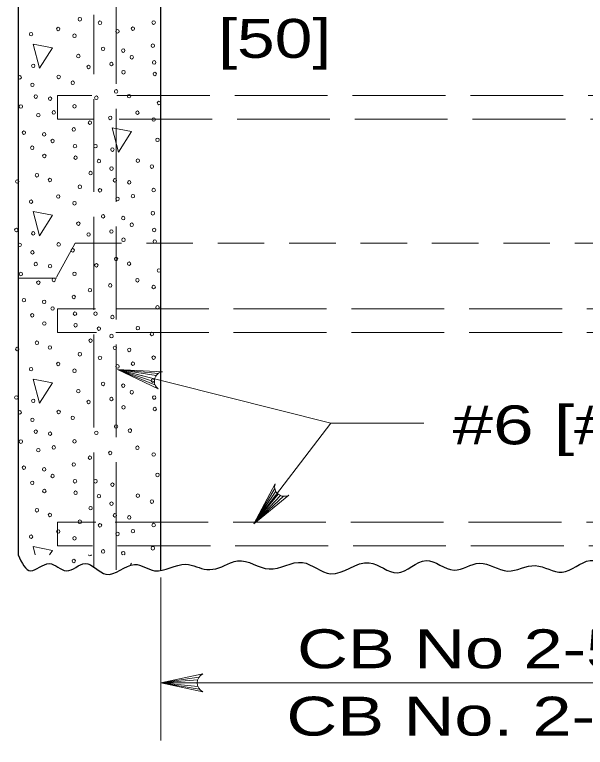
# Model space of a CAD drawing. Extents: x 1329.9 to 1363.9, y 715.5 to 737.5.
# Drawn here: x 1332.853 to 1335.139, y 728.698 to 731.635 of the extents above; entities that cross this region are included whole.
import ezdxf
from ezdxf.enums import TextEntityAlignment as Align

# ---------------------------------------------------------------- set-up
doc = ezdxf.new("R2010")
doc.units = 0
doc.header["$LTSCALE"] = 0.062
doc.linetypes.add('LONG_DASHED', pattern=[7.5, 6, -1.5])
doc.linetypes.add('MEDIUM_DASHED', pattern=[4.5, 3, -1.5])
doc.layers.add('1', color=7, linetype='Continuous', lineweight=13)

msp = doc.modelspace()

# ---------------------------------------------------------------- linework, layer by layer
at = {"layer": '1', "lineweight": 25}
for p, q in [((1333.43842, 729.84383), (1333.43842, 733.47708)), ((1332.86692, 732.80092), (1332.86692, 729.46942))]:
    msp.add_line(p, q, dxfattribs=at)
at = {"layer": '1', "linetype": 'LONG_DASHED'}
for p, q in [((1333.16925, 729.50833), (1333.16925, 731.63508)), ((1333.02425, 731.31067), (1333.02425, 731.21567)), ((1333.02425, 731.31067), (1333.16242, 731.31067)), ((1333.26267, 731.31067), (1338.07467, 731.31067)), ((1333.02425, 731.21567), (1333.167, 731.21567)), ((1333.27175, 731.21567), (1338.07467, 731.21567)), ((1333.02425, 730.45583), (1333.02425, 730.36083)), ((1333.02425, 730.45583), (1333.17608, 730.45583)), ((1333.25808, 730.45583), (1338.07925, 730.45583)), ((1333.02425, 730.36083), (1333.18067, 730.36083)), ((1333.25808, 730.36083), (1338.09292, 730.36083)), ((1333.02425, 729.60092), (1333.02425, 729.50592)), ((1333.02425, 729.60092), (1333.17833, 729.60092)), ((1333.25575, 729.60092), (1338.07692, 729.60092)), ((1333.02425, 729.50592), (1333.16467, 729.50592)), ((1333.26492, 729.50592), (1338.07692, 729.50592))]:
    msp.add_line(p, q, dxfattribs=at)
at = {"layer": '1', "linetype": 'MEDIUM_DASHED'}
for p, q in [((1333.095, 730.71958), (1333.02067, 730.58333)), ((1332.86708, 730.57925), (1333.02067, 730.57925))]:
    msp.add_line(p, q, dxfattribs=at)
at = {"layer": '1'}
for p, q in [((1333.265, 730.21225), (1334.11917, 729.997)), ((1333.41358, 730.175), (1333.265, 730.21225)), ((1333.41983, 730.18825), (1333.265, 730.21225)), ((1333.42833, 730.19683), (1333.265, 730.21225)), ((1333.41242, 730.16358), (1333.265, 730.21225)), ((1333.415, 730.1515), (1333.265, 730.21225)), ((1333.81167, 729.59417), (1334.11917, 729.997)), ((1334.49225, 729.997), (1334.11917, 729.997)), ((1333.89508, 729.7355), (1333.81167, 729.59417)), ((1333.89925, 729.72417), (1333.81167, 729.59417)), ((1333.90858, 729.71283), (1333.81167, 729.59417)), ((1333.91842, 729.707), (1333.81167, 729.59417)), ((1333.93042, 729.70417), (1333.81167, 729.59417)), ((1333.00408, 729.48742), (1332.92617, 729.50258)), ((1332.92617, 729.50258), (1332.93483, 729.46942)), ((1332.99258, 729.46942), (1333.00408, 729.48742)), ((1333.3165, 729.429), (1333.32117, 729.4365)), ((1333.43842, 729.37808), (1333.43842, 728.82842)), ((1333.43842, 729.37542), (1333.43842, 728.72567)), ((1333.59075, 728.97883), (1333.43842, 728.95625)), ((1333.58558, 728.96767), (1333.43842, 728.95625)), ((1333.584, 728.95625), (1333.43842, 728.95625)), ((1333.58667, 728.94183), (1333.43842, 728.95625)), ((1333.5925, 728.93133), (1333.43842, 728.95625)), ((1337.23308, 728.95625), (1333.43842, 728.95625))]:
    msp.add_line(p, q, dxfattribs=at)
at = {"layer": '1', "linetype": 'LONG_DASHED'}
for points in [[(1333.259, 729.40917), (1333.259, 729.46942), (1333.259, 733.37567)], [(1333.16925, 729.41842), (1333.16925, 729.46942), (1333.16925, 729.50833)]]:
    msp.add_lwpolyline(points, dxfattribs=at)
at = {"layer": '1'}
for points in [[(1332.92617, 731.5175), (1332.95175, 731.42017), (1333.00408, 731.50233)], [(1333.24333, 731.18167), (1333.269, 731.08433), (1333.32117, 731.1665)], [(1332.92617, 730.84592), (1332.95175, 730.7485), (1333.00408, 730.83067)], [(1332.92617, 730.17425), (1332.95175, 730.07692), (1333.00408, 730.15908)]]:
    msp.add_lwpolyline(points, close=True, dxfattribs=at)
at = {"layer": '1', "linetype": 'MEDIUM_DASHED'}
msp.add_lwpolyline([(1333.095, 730.71958), (1338.24792, 730.71958), (1338.32433, 730.57925)], dxfattribs=at)
at = {"layer": '1'}
for points in [[(1333.44533, 730.20358), (1333.265, 730.21225), (1333.42808, 730.13483)], [(1333.89625, 729.75375), (1333.81167, 729.59417), (1333.95108, 729.70892)], [(1333.60667, 728.92067), (1333.43842, 728.95625), (1333.60667, 728.99192)]]:
    msp.add_lwpolyline(points, dxfattribs=at)
at = {"layer": '1', "lineweight": 25}
msp.add_lwpolyline([(1333.43842, 729.40858), (1333.43842, 729.46942), (1333.43842, 729.84383)], dxfattribs=at)
at = {"layer": '1'}
for centre, start, end in [((1333.45059, 730.16568), 98.01033, 233.83646), ((1333.93272, 729.74239), 162.86757, 298.6937)]:
    msp.add_arc(centre, 0.03822, start, end, dxfattribs=at)
for centre, major_axis in [((1333.11378, 731.61691), (0, 0.00718)), ((1333.19456, 731.6027), (0, 0.00718)), ((1333.40957, 731.60354), (0, 0.00718)), ((1332.91849, 731.55703), (0, 0.00718)), ((1333.02724, 731.5779), (0, 0.00718)), ((1333.26477, 731.56822), (0, 0.00718)), ((1333.32647, 731.57913), (0, 0.00718)), ((1333.09237, 731.5507), (0, 0.00718)), ((1333.20715, 731.49814), (0, 0.00718)), ((1333.40645, 731.51079), (0, 0.00718)), ((1333.10781, 731.4691), (0, 0.00718)), ((1333.28798, 731.49115), (0, 0.00718)), ((1333.32165, 731.46456), (0, 0.00718)), ((1333.24056, 731.43736), (0, 0.00718)), ((1333.41158, 731.44368), (0, 0.00718)), ((1332.92706, 731.43008), (0, 0.00718)), ((1333.14894, 731.42555), (0, 0.00718)), ((1332.87314, 731.38385), (0, 0.00718)), ((1333.02899, 731.38564), (0, 0.00718)), ((1333.28882, 731.40439), (0, 0.00718)), ((1333.41412, 731.39745), (0, 0.00718)), ((1332.92362, 731.35391), (0, 0.00718)), ((1333.0855, 731.36208), (0, 0.00718)), ((1333.25885, 731.32732), (0, 0.00718)), ((1332.93737, 731.30678), (0, 0.00718)), ((1332.99473, 731.29855), (0, 0.00718)), ((1333.18003, 731.30197), (0, 0.00718)), ((1333.31108, 731.30829), (0, 0.00718)), ((1332.87736, 731.26687), (0, 0.00718)), ((1333.09237, 731.26771), (0, 0.00718)), ((1333.43098, 731.28109), (0, 0.00718)), ((1332.94757, 731.2324), (0, 0.00718)), ((1333.00927, 731.24331), (0, 0.00718)), ((1333.34444, 731.24208), (0, 0.00718)), ((1333.15428, 731.20217), (0, 0.00718)), ((1333.23569, 731.2212), (0, 0.00718)), ((1333.40957, 731.21488), (0, 0.00718)), ((1333.08925, 731.17497), (0, 0.00718)), ((1332.88995, 731.16232), (0, 0.00718)), ((1332.97078, 731.15533), (0, 0.00718)), ((1333.00446, 731.12874), (0, 0.00718)), ((1333.42501, 731.13327), (0, 0.00718)), ((1332.92336, 731.10154), (0, 0.00718)), ((1333.09438, 731.10786), (0, 0.00718)), ((1333.17664, 731.10786), (0, 0.00718)), ((1333.24426, 731.09426), (0, 0.00718)), ((1332.97163, 731.06857), (0, 0.00718)), ((1333.09692, 731.06163), (0, 0.00718)), ((1333.19033, 731.04803), (0, 0.00718)), ((1333.34619, 731.04982), (0, 0.00718)), ((1333.4027, 731.02626), (0, 0.00718)), ((1333.15687, 730.99995), (0, 0.00718)), ((1333.24082, 731.01809), (0, 0.00718)), ((1332.86283, 730.96614), (0, 0.00718)), ((1332.94165, 730.9915), (0, 0.00718)), ((1332.99388, 730.97247), (0, 0.00718)), ((1333.25457, 730.97096), (0, 0.00718)), ((1333.11378, 730.94527), (0, 0.00718)), ((1333.31193, 730.96273), (0, 0.00718)), ((1333.02724, 730.90626), (0, 0.00718)), ((1333.19456, 730.93105), (0, 0.00718)), ((1333.32647, 730.90749), (0, 0.00718)), ((1333.40957, 730.93189), (0, 0.00718)), ((1332.91849, 730.88538), (0, 0.00718)), ((1333.09237, 730.87905), (0, 0.00718)), ((1333.26477, 730.89657), (0, 0.00718)), ((1333.20715, 730.8265), (0, 0.00718)), ((1333.28798, 730.8195), (0, 0.00718)), ((1333.40645, 730.83915), (0, 0.00718)), ((1333.10781, 730.79745), (0, 0.00718)), ((1333.32165, 730.79292), (0, 0.00718)), ((1332.85944, 730.77204), (0, 0.00718)), ((1333.24056, 730.76571), (0, 0.00718)), ((1333.41158, 730.77204), (0, 0.00718)), ((1332.92706, 730.75844), (0, 0.00718)), ((1333.14894, 730.7539), (0, 0.00718)), ((1333.28882, 730.73275), (0, 0.00718)), ((1332.87314, 730.71221), (0, 0.00718)), ((1333.02899, 730.714), (0, 0.00718)), ((1333.41412, 730.72581), (0, 0.00718)), ((1332.92362, 730.68226), (0, 0.00718)), ((1333.0855, 730.69043), (0, 0.00718)), ((1333.25885, 730.65568), (0, 0.00718)), ((1332.93737, 730.63514), (0, 0.00718)), ((1332.99473, 730.62691), (0, 0.00718)), ((1333.18003, 730.63032), (0, 0.00718)), ((1333.31108, 730.63665), (0, 0.00718)), ((1332.87736, 730.59523), (0, 0.00718)), ((1333.09237, 730.59607), (0, 0.00718)), ((1333.43098, 730.60945), (0, 0.00718)), ((1332.94757, 730.56075), (0, 0.00718)), ((1333.00927, 730.57167), (0, 0.00718)), ((1333.34444, 730.57043), (0, 0.00718)), ((1333.15428, 730.53053), (0, 0.00718)), ((1333.23569, 730.54956), (0, 0.00718)), ((1333.40957, 730.54323), (0, 0.00718)), ((1333.08925, 730.50333), (0, 0.00718)), ((1332.88995, 730.49068), (0, 0.00718)), ((1332.97078, 730.48368), (0, 0.00718)), ((1333.00446, 730.45709), (0, 0.00718)), ((1333.09438, 730.43622), (0, 0.00718)), ((1333.17664, 730.43622), (0, 0.00718)), ((1333.42501, 730.46163), (0, 0.00718)), ((1332.92336, 730.42989), (0, 0.00718)), ((1333.24426, 730.42262), (0, 0.00718)), ((1332.97163, 730.39693), (0, 0.00718)), ((1333.09692, 730.38998), (0, 0.00718)), ((1333.34619, 730.37818), (0, 0.00718)), ((1333.19033, 730.37638), (0, 0.00718)), ((1333.4027, 730.35461), (0, 0.00718)), ((1332.94165, 730.31985), (0, 0.00718)), ((1333.15687, 730.32831), (0, 0.00718)), ((1333.24082, 730.34644), (0, 0.00718)), ((1332.86283, 730.2945), (0, 0.00718)), ((1332.99388, 730.30082), (0, 0.00718)), ((1333.25457, 730.29931), (0, 0.00718)), ((1333.31193, 730.29109), (0, 0.00718)), ((1333.11378, 730.27362), (0, 0.00718)), ((1333.19456, 730.25941), (0, 0.00718)), ((1333.40957, 730.26025), (0, 0.00718)), ((1333.02724, 730.23461), (0, 0.00718)), ((1333.32647, 730.23584), (0, 0.00718)), ((1332.91849, 730.21373), (0, 0.00718)), ((1333.09237, 730.20741), (0, 0.00718)), ((1333.26477, 730.22493), (0, 0.00718)), ((1333.20715, 730.15485), (0, 0.00718)), ((1333.28798, 730.14786), (0, 0.00718)), ((1333.40645, 730.1675), (0, 0.00718)), ((1333.10781, 730.1258), (0, 0.00718)), ((1333.32165, 730.12127), (0, 0.00718)), ((1332.85944, 730.10039), (0, 0.00718)), ((1332.92706, 730.08679), (0, 0.00718)), ((1333.24056, 730.09407), (0, 0.00718)), ((1333.14894, 730.08226), (0, 0.00718)), ((1333.28882, 730.0611), (0, 0.00718)), ((1333.41412, 730.05416), (0, 0.00718)), ((1332.87314, 730.04056), (0, 0.00718)), ((1333.02899, 730.04235), (0, 0.00718)), ((1332.92362, 730.01062), (0, 0.00718)), ((1333.0855, 730.01879), (0, 0.00718)), ((1333.25885, 729.98403), (0, 0.00718)), ((1333.31448, 729.96761), (-0.00095, 0.00712)), ((1332.93737, 729.96349), (0, 0.00718)), ((1332.99473, 729.95526), (0, 0.00718)), ((1333.18003, 729.95868), (0, 0.00718)), ((1332.87736, 729.92358), (0, 0.00718)), ((1333.09237, 729.92442), (0, 0.00718)), ((1332.94757, 729.88911), (0, 0.00718)), ((1333.00927, 729.90002), (0, 0.00718)), ((1333.23569, 729.87791), (0, 0.00718)), ((1333.34444, 729.89879), (0, 0.00718)), ((1333.15428, 729.85888), (0, 0.00718)), ((1333.40957, 729.87159), (0, 0.00718)), ((1332.88995, 729.81903), (0, 0.00718)), ((1333.08925, 729.83168), (0, 0.00718)), ((1332.97078, 729.81203), (0, 0.00718)), ((1333.42501, 729.78998), (0, 0.00718)), ((1333.00446, 729.78545), (0, 0.00718)), ((1333.09438, 729.76457), (0, 0.00718)), ((1333.17664, 729.76457), (0, 0.00718)), ((1332.92336, 729.75825), (0, 0.00718)), ((1333.24426, 729.75097), (0, 0.00718)), ((1332.97163, 729.72528), (0, 0.00718)), ((1333.09692, 729.71834), (0, 0.00718)), ((1333.19033, 729.70474), (0, 0.00718)), ((1333.34619, 729.70653), (0, 0.00718)), ((1333.24082, 729.67479), (0, 0.00718)), ((1333.4027, 729.68297), (0, 0.00718)), ((1332.94165, 729.64821), (0, 0.00718)), ((1333.15687, 729.65666), (0, 0.00718)), ((1332.99388, 729.62918), (0, 0.00718)), ((1333.25457, 729.62767), (0, 0.00718)), ((1333.31193, 729.61944), (0, 0.00718)), ((1333.11378, 729.60198), (0, 0.00718)), ((1333.19456, 729.58776), (0, 0.00718)), ((1333.40957, 729.5886), (0, 0.00718)), ((1333.02724, 729.56297), (0, 0.00718)), ((1333.32647, 729.5642), (0, 0.00718)), ((1332.91849, 729.54209), (0, 0.00718)), ((1333.09237, 729.53576), (0, 0.00718)), ((1333.26477, 729.55328), (0, 0.00718)), ((1333.40645, 729.49586), (0, 0.00718)), ((1333.20715, 729.48321), (0, 0.00718)), ((1333.08925, 729.44498), (0, 0.00718))]:
    msp.add_ellipse(centre, major_axis=major_axis, ratio=0.944544, dxfattribs=at)
for centre, major_axis, start_param, end_param in [((1333.41158, 730.10039), (0, 0.00718), 4.7796971, 10.5477077), ((1333.28798, 729.47621), (0, 0.00718), 3.4875052, 9.0788653), ((1333.15428, 729.47219), (0, 0.00718), 1.9609233, 4.322262), ((1333.6203, 728.95629), (0, 0.03844), 0.3855052, 2.7561184)]:
    msp.add_ellipse(centre, major_axis=major_axis, ratio=0.944544, start_param=start_param, end_param=end_param, dxfattribs=at)
at = {"layer": '1', "lineweight": 25}
for points in [[(1332.86692, 729.46942), (1332.91758, 729.40558), (1332.99125, 729.43417), (1333.06017, 729.40525), (1333.13483, 729.43483), (1333.21858, 729.39133), (1333.33333, 729.43083), (1333.41342, 729.40583), (1333.53833, 729.43175), (1333.62308, 729.41075), (1333.71783, 729.43742)], [(1333.71783, 729.43742), (1333.74617, 729.44542), (1333.87192, 729.41275), (1334.00608, 729.43875), (1334.11883, 729.3935), (1334.27358, 729.438), (1334.38633, 729.39758), (1334.501, 729.44683), (1334.61375, 729.40833), (1334.71533, 729.43617), (1334.828, 729.4045), (1334.93892, 729.42642), (1335.04608, 729.39958), (1335.15892, 729.44692), (1335.307, 729.40475), (1335.43475, 729.43842), (1335.53625, 729.40375), (1335.72358, 729.43092), (1335.86242, 729.41792), (1335.96125, 729.43683), (1336.07208, 729.39742), (1336.18867, 729.436), (1336.31817, 729.3985), (1336.50175, 729.42075), (1336.6145, 729.40175), (1336.76542, 729.42783), (1336.854, 729.38433), (1337.004, 729.42892), (1337.1335, 729.38567), (1337.34833, 729.41017)]]:
    msp.add_spline(points, degree=3, dxfattribs=at)

# ---------------------------------------------------------------- texts
at = {"layer": '1', "width": 1.3}
msp.add_text('[50]', height=0.156, dxfattribs=at).set_placement((1333.89471, 731.462), align=Align.CENTER)
at = {"layer": '1'}
for s, width, p in [('#6 [#19M] bars', 1.4, (1334.60733, 729.9125)), ('CB No 2-5 = 5\'-0" [1500]', 1.35, (1333.98433, 729.01475)), ('CB No. 2-6 = 6\'-0" [1800]', 1.35, (1333.94167, 728.74467))]:
    msp.add_text(s, height=0.156, dxfattribs=dict(at, width=width)).set_placement(p)

doc.saveas('drawing.dxf')
